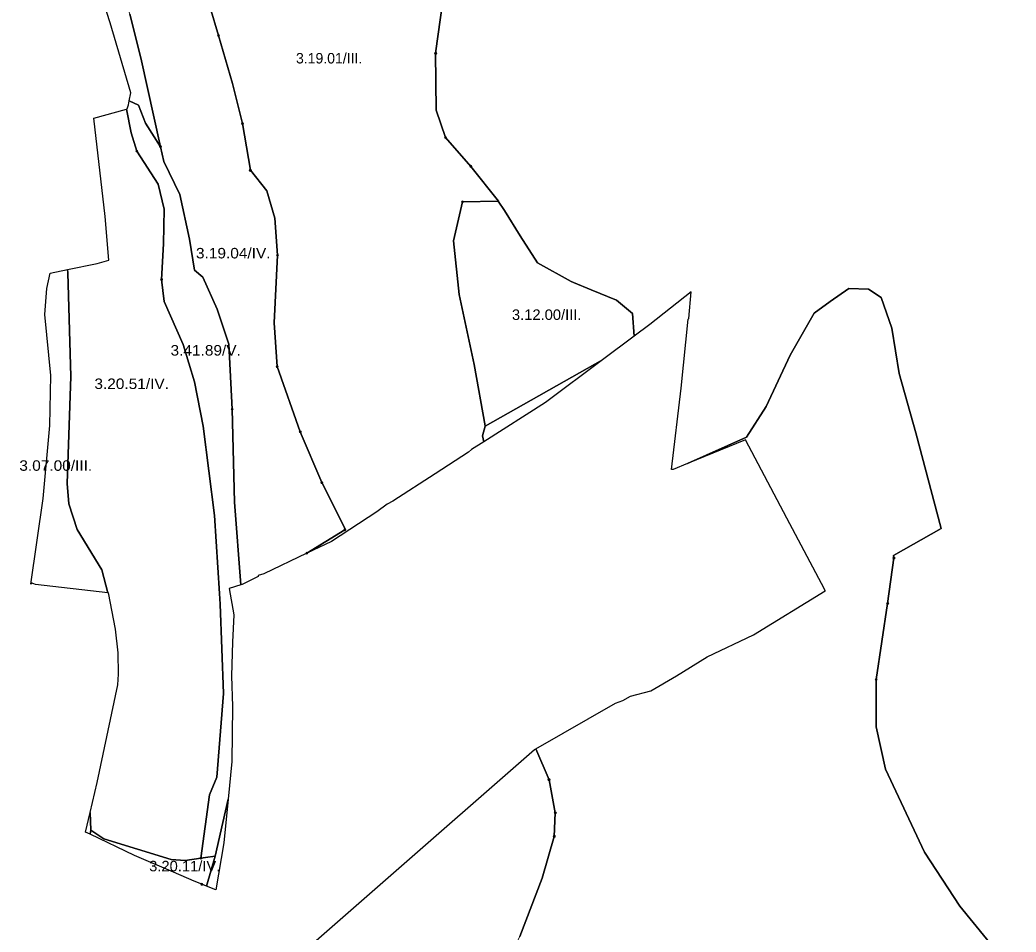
# Model space of a CAD drawing. Extents: x -650455 to -642254, y -1075222 to -1066610.
# Drawn here: x -649469 to -648519, y -1069005 to -1068135 of the extents above; entities that cross this region are included whole.
import ezdxf
from ezdxf.enums import TextEntityAlignment as Align

# ---------------------------------------------------------------- set-up
doc = ezdxf.new("R2010")
doc.units = 0
doc.header["$LTSCALE"] = 4
doc.header["$PDMODE"] = 32
doc.header["$PDSIZE"] = 2
for name, color, linetype, lineweight in [('1', 7, 'Continuous', 25), ('11', 7, 'Continuous', 13), ('13', 7, 'Continuous', 13), ('14', 7, 'Continuous', 13), ('15', 7, 'Continuous', 13)]:
    doc.layers.add(name, color=color, linetype=linetype, lineweight=lineweight)
doc.layers.add('2', color=7, linetype='Continuous')

msp = doc.modelspace()

# ---------------------------------------------------------------- linework, layer by layer
at = {"layer": '1'}
for points in [[(-649364.5, -1068129.5), (-649354, -1068171.001), (-649335.143, -1068255.857), (-649349.403, -1068233.447), (-649356.096, -1068216.124), (-649364.868, -1068211.996), (-649363.265, -1068204.401), (-649383.086, -1068137.741), (-649399.254, -1068087.078)], [(-649065.71, -1068116.69), (-649072.632, -1068166.715), (-649072.238, -1068220.849), (-649063.183, -1068247.029), (-649039.167, -1068274.588), (-649012.789, -1068307.66), (-649013.037, -1068307.665), (-649047.041, -1068308.446), (-649055.703, -1068345.651), (-649050.191, -1068396.833), (-649036.018, -1068463.565), (-649025.438, -1068521.95), (-649025.388, -1068522.227), (-649025.39, -1068522.234), (-649027.986, -1068531.621), (-649026.606, -1068537.189), (-649038.312, -1068544.611)], [(-648900.191, -1068402.148), (-648924.207, -1068392.305), (-648941.005, -1068385.449), (-648943.498, -1068384.432), (-648975.388, -1068366.715), (-648991.923, -1068340.73), (-649006.884, -1068316.714), (-649013.037, -1068307.665), (-649012.789, -1068307.66), (-649039.167, -1068274.588), (-649063.183, -1068247.029), (-649072.238, -1068220.849), (-649072.632, -1068166.715), (-649065.71, -1068116.69)], [(-649287.592, -1068123.014), (-649279.725, -1068149.82), (-649266.333, -1068195.454), (-649256.884, -1068233.841), (-649249.403, -1068278.329), (-649233.655, -1068298.014), (-649226.175, -1068323.997), (-649223.419, -1068359.235), (-649226.569, -1068423.802), (-649223.813, -1068465.533), (-649201.766, -1068527.739), (-649181.293, -1068576.163), (-649158.789, -1068620.777), (-649159.246, -1068621.045), (-649195.499, -1068643.488), (-649236.455, -1068663.157), (-649241.818, -1068664.851), (-649241.959, -1068665.697), (-649257.342, -1068673.178), (-649258.439, -1068673.532), (-649264.364, -1068594.668), (-649266.726, -1068506.084), (-649269.876, -1068444.273), (-649280.899, -1068410.81), (-649294.679, -1068380.297), (-649302.531, -1068373.426), (-649307.5, -1068344), (-649316.5, -1068301.501), (-649332, -1068270.001), (-649335.143, -1068255.857), (-649354, -1068171.001), (-649364.5, -1068129.5)], [(-649038.312, -1068544.611), (-649041.276, -1068547.15), (-649073.059, -1068567.675), (-649113.392, -1068593.723), (-649119.037, -1068596.687), (-649128.634, -1068603.885), (-649172.101, -1068632.25), (-649195.499, -1068643.488), (-649159.246, -1068621.045), (-649158.789, -1068620.777), (-649181.293, -1068576.163), (-649201.766, -1068527.739), (-649223.813, -1068465.533), (-649226.569, -1068423.802), (-649223.419, -1068359.235), (-649226.175, -1068323.997), (-649233.655, -1068298.014), (-649249.403, -1068278.329), (-649256.884, -1068233.841), (-649266.333, -1068195.454), (-649279.725, -1068149.82), (-649287.592, -1068123.014)], [(-649366.961, -1068219.834), (-649365.689, -1068215.888), (-649364.868, -1068211.996), (-649356.096, -1068216.124), (-649349.403, -1068233.447), (-649335.143, -1068255.857)], [(-649296.514, -1068934.397), (-649311.5, -1068936.501), (-649325, -1068935.5), (-649389, -1068916.001), (-649401.5, -1068907.5), (-649402.128, -1068890.866), (-649395.364, -1068862.007), (-649375.747, -1068769.144), (-649375.042, -1068758.701), (-649375.465, -1068738.378), (-649377.865, -1068715.799), (-649384.682, -1068681.416), (-649385.338, -1068681.34), (-649391, -1068659.5), (-649414.5, -1068621.001), (-649422.5, -1068596.501), (-649424, -1068577.001), (-649420.5, -1068475.001), (-649423.5, -1068376), (-649423.738, -1068372.995), (-649395.365, -1068367.067), (-649384.287, -1068363.941), (-649387.979, -1068322.456), (-649398.773, -1068228.688), (-649367.606, -1068220.013), (-649367.523, -1068219.989), (-649363.183, -1068242.502), (-649357.671, -1068260.022), (-649337.199, -1068291.517), (-649331.687, -1068315.533), (-649332.081, -1068348.605), (-649334.049, -1068382.463), (-649331.687, -1068403.525), (-649313.577, -1068444.47), (-649302.553, -1068479.904), (-649294.285, -1068522.424), (-649283.655, -1068607.66), (-649278.819, -1068681.755), (-649278.144, -1068692.109), (-649274.994, -1068777.344)], [(-649335.143, -1068255.857), (-649332, -1068270.001), (-649316.5, -1068301.501), (-649307.5, -1068344), (-649302.531, -1068373.426), (-649294.679, -1068380.297), (-649280.899, -1068410.81), (-649269.876, -1068444.273), (-649266.726, -1068506.084), (-649264.364, -1068594.668), (-649258.439, -1068673.532), (-649269.72, -1068677.182), (-649265.289, -1068702.349), (-649266.397, -1068728.271), (-649267.505, -1068760.486), (-649266.397, -1068789.681), (-649266.951, -1068842.029), (-649270.576, -1068878.136), (-649275.635, -1068900.275), (-649283, -1068932.501), (-649292.13, -1068933.782), (-649296.514, -1068934.397), (-649288.38, -1068873.998), (-649281.293, -1068857.069), (-649274.994, -1068777.344), (-649278.144, -1068692.109), (-649278.819, -1068681.755), (-649283.655, -1068607.66), (-649294.285, -1068522.424), (-649302.553, -1068479.904), (-649313.577, -1068444.47), (-649331.687, -1068403.525), (-649334.049, -1068382.463), (-649332.081, -1068348.605), (-649331.687, -1068315.533), (-649337.199, -1068291.517), (-649357.671, -1068260.022), (-649363.183, -1068242.502), (-649367.523, -1068219.989), (-649366.961, -1068219.834)], [(-648519, -1069046.001), (-648572.5, -1068980), (-648606.5, -1068928.501), (-648643.5, -1068849.5), (-648652.5, -1068809), (-648652.5, -1068764), (-648641.5, -1068691.5), (-648635.5, -1068648), (-648635.9, -1068645.645), (-648590.348, -1068620.06), (-648614.758, -1068528.722), (-648630.506, -1068472.029), (-648637.593, -1068428.723), (-648647.829, -1068399.588), (-648659.64, -1068391.715), (-648678.537, -1068390.926), (-648696.271, -1068403.593), (-648711.608, -1068414.548), (-648734.443, -1068454.707), (-648757.278, -1068503.526), (-648776.095, -1068532.88), (-648832.283, -1068557.956), (-648846.238, -1068563.662), (-648847.649, -1068563.522), (-648838.476, -1068486.043), (-648831.843, -1068420.418), (-648831.137, -1068419.713), (-648829.017, -1068394.254), (-648868.395, -1068425.359), (-648883.259, -1068436.507), (-648884.836, -1068414.747), (-648900.191, -1068402.148)], [(-649274.994, -1068777.344), (-649281.293, -1068857.069), (-649288.38, -1068873.998), (-649296.514, -1068934.397)], [(-649260.164, -1069077.084), (-648978.256, -1068830.599), (-648977.155, -1068829.971), (-648964.5, -1068859.501), (-648958.5, -1068891), (-648959.5, -1068913.501), (-648971, -1068953.501), (-648992.5, -1069009.001)]]:
    msp.add_lwpolyline(points, dxfattribs=at)
for points in [[(-648883.259, -1068436.507), (-648913.435, -1068459.138), (-649025.39, -1068522.234), (-649025.388, -1068522.227), (-649025.438, -1068521.95), (-649036.018, -1068463.565), (-649050.191, -1068396.833), (-649055.703, -1068345.651), (-649047.041, -1068308.446), (-649013.037, -1068307.665), (-649006.884, -1068316.714), (-648991.923, -1068340.73), (-648975.388, -1068366.715), (-648943.498, -1068384.432), (-648941.005, -1068385.449), (-648924.207, -1068392.305), (-648900.191, -1068402.148), (-648884.836, -1068414.747)], [(-649391, -1068659.5), (-649385.338, -1068681.34), (-649454.356, -1068673.319), (-649457.602, -1068672.19), (-649458.872, -1068672.895), (-649447.017, -1068591.325), (-649440.525, -1068521.608), (-649439.678, -1068473.907), (-649445.359, -1068415.94), (-649443.655, -1068390.935), (-649440.246, -1068376.444), (-649423.738, -1068372.995), (-649423.5, -1068376), (-649420.5, -1068475.001), (-649424, -1068577.001), (-649422.5, -1068596.501), (-649414.5, -1068621.001)], [(-648967.748, -1068499.874), (-649026.606, -1068537.189), (-649027.986, -1068531.621), (-649025.39, -1068522.234), (-648913.435, -1068459.138)], [(-649274.736, -1068919.577), (-649282.181, -1068964.581), (-649291.173, -1068961), (-649283, -1068932.501), (-649275.635, -1068900.275), (-649270.576, -1068878.136)], [(-649401.5, -1068907.5), (-649402.052, -1068911.581), (-649406.488, -1068909.47), (-649402.128, -1068890.866)], [(-649296.514, -1068934.397), (-649292.13, -1068933.782), (-649283, -1068932.501), (-649291.173, -1068961), (-649295.705, -1068959.195), (-649302.884, -1068956.114), (-649322.56, -1068947.665), (-649359.902, -1068931.634), (-649402.052, -1068911.581), (-649401.5, -1068907.5), (-649389, -1068916.001), (-649325, -1068935.5), (-649311.5, -1068936.501)]]:
    msp.add_lwpolyline(points, close=True, dxfattribs=at)
at = {"layer": '11'}
for p, q in [((-648635.5, -1068648), (-648641.5, -1068691.5)), ((-648641.5, -1068691.5), (-648652.5, -1068764))]:
    msp.add_line(p, q, dxfattribs=at)
for points in [[(-649366.332, -1067849.194), (-649320.663, -1067841.715), (-649267.12, -1067848.408), (-649248.33, -1067854.452), (-649216.333, -1067864.747), (-649172.632, -1067909.235), (-649152.947, -1067946.243), (-649153.622, -1067946.381), (-649131.687, -1067981.479), (-649118.254, -1068000), (-649105.703, -1068017.306), (-649067.907, -1068076.753), (-649063.97, -1068104.117), (-649065.71, -1068116.69), (-649072.632, -1068166.715), (-649072.238, -1068220.849), (-649063.183, -1068247.029), (-649039.167, -1068274.588)], [(-649039.167, -1068274.588), (-649012.789, -1068307.66), (-649013.037, -1068307.665), (-649006.884, -1068316.714), (-648991.923, -1068340.73), (-648975.388, -1068366.715), (-648943.498, -1068384.432), (-648941.005, -1068385.449), (-648924.207, -1068392.305), (-648900.191, -1068402.148), (-648884.836, -1068414.747), (-648883.259, -1068436.507), (-648868.395, -1068425.359), (-648829.017, -1068394.254), (-648831.137, -1068419.713), (-648831.843, -1068420.418), (-648838.476, -1068486.043), (-648847.649, -1068563.522), (-648846.238, -1068563.662), (-648832.283, -1068557.956), (-648776.095, -1068532.88), (-648757.278, -1068503.526), (-648734.443, -1068454.707), (-648711.608, -1068414.548), (-648696.271, -1068403.593), (-648678.537, -1068390.926), (-648659.64, -1068391.715), (-648647.829, -1068399.588), (-648637.593, -1068428.723), (-648630.506, -1068472.029), (-648614.758, -1068528.722), (-648590.348, -1068620.06), (-648635.9, -1068645.645), (-648635.5, -1068648)], [(-648519, -1069046.001), (-648572.5, -1068980), (-648606.5, -1068928.501), (-648643.5, -1068849.5), (-648652.5, -1068809), (-648652.5, -1068764), (-648641.5, -1068691.5), (-648635.5, -1068648), (-648635.9, -1068645.645), (-648590.348, -1068620.06), (-648614.758, -1068528.722), (-648630.506, -1068472.029), (-648637.593, -1068428.723), (-648647.829, -1068399.588), (-648659.64, -1068391.715), (-648678.537, -1068390.926), (-648696.271, -1068403.593), (-648711.608, -1068414.548), (-648734.443, -1068454.707), (-648757.278, -1068503.526), (-648776.095, -1068532.88), (-648832.283, -1068557.956), (-648777.008, -1068535.353), (-648737.524, -1068610.084), (-648701.673, -1068677.917), (-648700.969, -1068679.249), (-648769.362, -1068721.328), (-648813.675, -1068742.354), (-648842.933, -1068760.541), (-648867.319, -1068774.603), (-648886.764, -1068779.71), (-648894.138, -1068783.896), (-648900.973, -1068786.476), (-648977.155, -1068829.971)], [(-648652.5, -1068764), (-648652.5, -1068809), (-648643.5, -1068849.5), (-648606.5, -1068928.501), (-648572.5, -1068980), (-648519, -1069046.001)], [(-648977.155, -1068829.971), (-648964.5, -1068859.501), (-648958.5, -1068891), (-648959.5, -1068913.501)], [(-648959.5, -1068913.501), (-648971, -1068953.501), (-648992.5, -1069009.001), (-649028, -1069075.501), (-649064, -1069119.501), (-649098.5, -1069146), (-649179.5, -1069197.5), (-649201.5, -1069217.5), (-649236.5, -1069258), (-649253, -1069293.001), (-649258.5, -1069342.001), (-649257.5, -1069379.5), (-649267.5, -1069409), (-649323.5, -1069487.501), (-649342.5, -1069528.001), (-649348, -1069550.5), (-649346, -1069559.5), (-649338.5, -1069573.501), (-649326.906, -1069580.081), (-649320, -1069584.001), (-649255.5, -1069595.5)]]:
    msp.add_lwpolyline(points, dxfattribs=at)
at = {"layer": '11', "lineweight": 25}
for points in [[(-648886.764, -1068779.71), (-648867.319, -1068774.603), (-648842.933, -1068760.541), (-648813.675, -1068742.354), (-648769.362, -1068721.328), (-648700.969, -1068679.249), (-648701.673, -1068677.917), (-648737.524, -1068610.084), (-648777.008, -1068535.353), (-648832.283, -1068557.956), (-648776.095, -1068532.88), (-648757.278, -1068503.526), (-648734.443, -1068454.707), (-648711.608, -1068414.548), (-648696.271, -1068403.593), (-648678.537, -1068390.926), (-648659.64, -1068391.715), (-648647.829, -1068399.588), (-648637.593, -1068428.723), (-648630.506, -1068472.029), (-648614.758, -1068528.722)], [(-648614.758, -1068528.722), (-648590.348, -1068620.06), (-648635.9, -1068645.645), (-648635.5, -1068648), (-648641.5, -1068691.5), (-648652.5, -1068764), (-648652.5, -1068809), (-648643.5, -1068849.5), (-648606.5, -1068928.501), (-648572.5, -1068980), (-648519, -1069046.001)], [(-648992.5, -1069009.001), (-648971, -1068953.501), (-648959.5, -1068913.501), (-648958.5, -1068891), (-648964.5, -1068859.501), (-648977.155, -1068829.971), (-648900.973, -1068786.476), (-648894.138, -1068783.896), (-648886.764, -1068779.71)]]:
    msp.add_lwpolyline(points, dxfattribs=at)
at = {"layer": '11'}
for p in [(-649039.167, -1068274.588), (-648635.5, -1068648), (-648641.5, -1068691.5), (-648652.5, -1068764), (-648959.5, -1068913.501)]:
    msp.add_point(p, dxfattribs=at)
at = {"layer": '13'}
for p, q in [((-649072.632, -1068166.715), (-649065.71, -1068116.69)), ((-649025.39, -1068522.234), (-648913.435, -1068459.138)), ((-649201.766, -1068527.739), (-649181.293, -1068576.163)), ((-649159.246, -1068621.045), (-649195.499, -1068643.488)), ((-648958.5, -1068891), (-648964.5, -1068859.501))]:
    msp.add_line(p, q, dxfattribs=at)
for points in [[(-649287.592, -1068123.014), (-649279.725, -1068149.82), (-649266.333, -1068195.454), (-649256.884, -1068233.841), (-649249.403, -1068278.329), (-649233.655, -1068298.014), (-649226.175, -1068323.997), (-649223.419, -1068359.235), (-649226.569, -1068423.802)], [(-649063.183, -1068247.029), (-649072.238, -1068220.849), (-649072.632, -1068166.715)], [(-649025.388, -1068522.227), (-649025.438, -1068521.95), (-649036.018, -1068463.565), (-649050.191, -1068396.833), (-649055.703, -1068345.651), (-649047.041, -1068308.446), (-649013.037, -1068307.665), (-649012.789, -1068307.66), (-649039.167, -1068274.588), (-649063.183, -1068247.029)], [(-649047.041, -1068308.446), (-649055.703, -1068345.651), (-649050.191, -1068396.833), (-649036.018, -1068463.565), (-649025.438, -1068521.95), (-649025.388, -1068522.227)], [(-648913.435, -1068459.138), (-648883.259, -1068436.507), (-648884.836, -1068414.747), (-648900.191, -1068402.148), (-648924.207, -1068392.305), (-648941.005, -1068385.449), (-648943.498, -1068384.432), (-648975.388, -1068366.715), (-648991.923, -1068340.73), (-649006.884, -1068316.714), (-649013.037, -1068307.665), (-649047.041, -1068308.446)], [(-649226.569, -1068423.802), (-649223.813, -1068465.533), (-649201.766, -1068527.739)], [(-649195.499, -1068643.488), (-649172.101, -1068632.25), (-649128.634, -1068603.885), (-649119.037, -1068596.687), (-649113.392, -1068593.723), (-649073.059, -1068567.675), (-649041.276, -1068547.15), (-649038.312, -1068544.611), (-649026.606, -1068537.189), (-649027.986, -1068531.621), (-649025.39, -1068522.234)], [(-649181.293, -1068576.163), (-649158.789, -1068620.777), (-649159.246, -1068621.045)], [(-648964.5, -1068859.501), (-648977.155, -1068829.971), (-648978.256, -1068830.599), (-649260.164, -1069077.084), (-649288.704, -1069124.951), (-649290.507, -1069162.185), (-649295.587, -1069197.042), (-649300.809, -1069224.704), (-649315.697, -1069282.325), (-649315.968, -1069283.372), (-649369.938, -1069306.536), (-649381.394, -1069310.889), (-649379.5, -1069353.501)], [(-648992.5, -1069009.001), (-648971, -1068953.501), (-648959.5, -1068913.501), (-648958.5, -1068891)]]:
    msp.add_lwpolyline(points, dxfattribs=at)
msp.add_lwpolyline([(-649385.338, -1068681.34), (-649391, -1068659.5), (-649414.5, -1068621.001), (-649422.5, -1068596.501), (-649424, -1068577.001), (-649420.5, -1068475.001), (-649423.5, -1068376), (-649423.738, -1068372.995), (-649440.246, -1068376.444), (-649443.655, -1068390.935), (-649445.359, -1068415.94), (-649439.678, -1068473.907), (-649440.525, -1068521.608), (-649447.017, -1068591.325), (-649458.872, -1068672.895), (-649457.602, -1068672.19), (-649454.356, -1068673.319)], close=True, dxfattribs=at)
for p in [(-649072.632, -1068166.715), (-649063.183, -1068247.029), (-649047.041, -1068308.446), (-649201.766, -1068527.739), (-649181.293, -1068576.163), (-649159.246, -1068621.045), (-649195.499, -1068643.488), (-648964.5, -1068859.501), (-648958.5, -1068891)]:
    msp.add_point(p, dxfattribs=at)
at = {"layer": '14'}
msp.add_line((-649249.403, -1068278.329), (-649256.884, -1068233.841), dxfattribs=at)
for points in [[(-649279.725, -1068149.82), (-649287.592, -1068123.014), (-649315.151, -1068075.573), (-649333.262, -1068052.344), (-649355.332, -1068063.38), (-649368.695, -1068070.06), (-649379.015, -1068084.351), (-649378.5, -1068085.5), (-649364.5, -1068129.5), (-649354, -1068171.001), (-649335.143, -1068255.857)], [(-649399.254, -1068087.078), (-649383.086, -1068137.741), (-649363.265, -1068204.401), (-649364.868, -1068211.996), (-649356.096, -1068216.124), (-649349.403, -1068233.447), (-649335.143, -1068255.857), (-649354, -1068171.001), (-649364.5, -1068129.5)], [(-649256.884, -1068233.841), (-649266.333, -1068195.454), (-649279.725, -1068149.82)], [(-649357.671, -1068260.022), (-649363.183, -1068242.502), (-649367.523, -1068219.989), (-649367.606, -1068220.013), (-649398.773, -1068228.688), (-649387.979, -1068322.456), (-649384.287, -1068363.941), (-649395.365, -1068367.067), (-649423.738, -1068372.995), (-649423.5, -1068376), (-649420.5, -1068475.001), (-649424, -1068577.001), (-649422.5, -1068596.501), (-649414.5, -1068621.001), (-649391, -1068659.5), (-649385.338, -1068681.34)], [(-649385.338, -1068681.34), (-649384.682, -1068681.416), (-649377.865, -1068715.799), (-649375.465, -1068738.378), (-649375.042, -1068758.701), (-649375.747, -1068769.144), (-649395.364, -1068862.007), (-649402.128, -1068890.866), (-649401.5, -1068907.5), (-649389, -1068916.001), (-649325, -1068935.5), (-649311.5, -1068936.501), (-649296.514, -1068934.397), (-649288.38, -1068873.998), (-649281.293, -1068857.069), (-649274.994, -1068777.344), (-649278.144, -1068692.109), (-649278.819, -1068681.755), (-649283.655, -1068607.66), (-649294.285, -1068522.424), (-649302.553, -1068479.904), (-649313.577, -1068444.47), (-649331.687, -1068403.525), (-649334.049, -1068382.463), (-649332.081, -1068348.605), (-649331.687, -1068315.533), (-649337.199, -1068291.517), (-649357.671, -1068260.022)], [(-649335.143, -1068255.857), (-649332, -1068270.001), (-649316.5, -1068301.501), (-649307.5, -1068344), (-649302.531, -1068373.426), (-649294.679, -1068380.297), (-649280.899, -1068410.81), (-649269.876, -1068444.273), (-649266.726, -1068506.084)], [(-649223.419, -1068359.235), (-649226.175, -1068323.997), (-649233.655, -1068298.014), (-649249.403, -1068278.329)], [(-649223.813, -1068465.533), (-649226.569, -1068423.802), (-649223.419, -1068359.235)], [(-649266.726, -1068506.084), (-649264.364, -1068594.668), (-649258.439, -1068673.532), (-649257.342, -1068673.178), (-649241.959, -1068665.697), (-649241.818, -1068664.851), (-649236.455, -1068663.157), (-649195.499, -1068643.488), (-649159.246, -1068621.045), (-649158.789, -1068620.777), (-649181.293, -1068576.163), (-649201.766, -1068527.739), (-649223.813, -1068465.533)]]:
    msp.add_lwpolyline(points, dxfattribs=at)
msp.add_lwpolyline([(-649295.705, -1068959.195), (-649291.173, -1068961), (-649283, -1068932.501), (-649292.13, -1068933.782), (-649296.514, -1068934.397), (-649311.5, -1068936.501), (-649325, -1068935.5), (-649389, -1068916.001), (-649401.5, -1068907.5), (-649402.052, -1068911.581), (-649359.902, -1068931.634), (-649322.56, -1068947.665), (-649302.884, -1068956.114)], close=True, dxfattribs=at)
for p in [(-649279.725, -1068149.82), (-649256.884, -1068233.841), (-649357.671, -1068260.022), (-649335.143, -1068255.857), (-649249.403, -1068278.329), (-649223.419, -1068359.235), (-649223.813, -1068465.533), (-649266.726, -1068506.084), (-649295.705, -1068959.195)]:
    msp.add_point(p, dxfattribs=at)
at = {"layer": '15'}
for points in [[(-649296.514, -1068934.397), (-649292.13, -1068933.782), (-649283, -1068932.501), (-649275.635, -1068900.275), (-649270.576, -1068878.136), (-649266.951, -1068842.029), (-649266.397, -1068789.681), (-649267.505, -1068760.486), (-649266.397, -1068728.271), (-649265.289, -1068702.349), (-649269.72, -1068677.182), (-649258.439, -1068673.532), (-649264.364, -1068594.668), (-649266.726, -1068506.084), (-649269.876, -1068444.273), (-649280.899, -1068410.81), (-649294.679, -1068380.297), (-649302.531, -1068373.426), (-649307.5, -1068344), (-649316.5, -1068301.501), (-649332, -1068270.001), (-649335.143, -1068255.857), (-649349.403, -1068233.447), (-649356.096, -1068216.124), (-649364.868, -1068211.996), (-649365.689, -1068215.888), (-649366.961, -1068219.834), (-649367.523, -1068219.989), (-649363.183, -1068242.502), (-649357.671, -1068260.022), (-649337.199, -1068291.517), (-649331.687, -1068315.533), (-649332.081, -1068348.605), (-649334.049, -1068382.463)], [(-649334.049, -1068382.463), (-649331.687, -1068403.525), (-649313.577, -1068444.47), (-649302.553, -1068479.904)], [(-649302.553, -1068479.904), (-649294.285, -1068522.424), (-649283.655, -1068607.66), (-649278.819, -1068681.755), (-649278.144, -1068692.109), (-649274.994, -1068777.344), (-649281.293, -1068857.069), (-649288.38, -1068873.998), (-649296.514, -1068934.397)]]:
    msp.add_lwpolyline(points, dxfattribs=at)
for p in [(-649334.049, -1068382.463), (-649296.514, -1068934.397)]:
    msp.add_point(p, dxfattribs=at)

# ---------------------------------------------------------------- texts
at = {"layer": '2'}
msp.add_text('3.19.01/III.', height=10, dxfattribs=at).set_placement((-649174.238, -1068176.453), align=Align.CENTER)
for s, width, p in [('3.19.04/IV.', 1.1, (-649265.691, -1068362.359)), ('3.12.00/III.', 1.05, (-648966.711, -1068421.015)), ('3.41.89/V.', 1.1, (-649291.986, -1068454.994)), ('3.20.51/IV.', 1.1, (-649362.588, -1068486.881)), ('3.07.00/III.', 1.1, (-649434.995, -1068564.898)), ('3.20.11/IV.', 1.05, (-649311.99, -1068946.86))]:
    msp.add_text(s, height=10, dxfattribs=dict(at, width=width)).set_placement(p, align=Align.CENTER)

doc.saveas('drawing.dxf')
